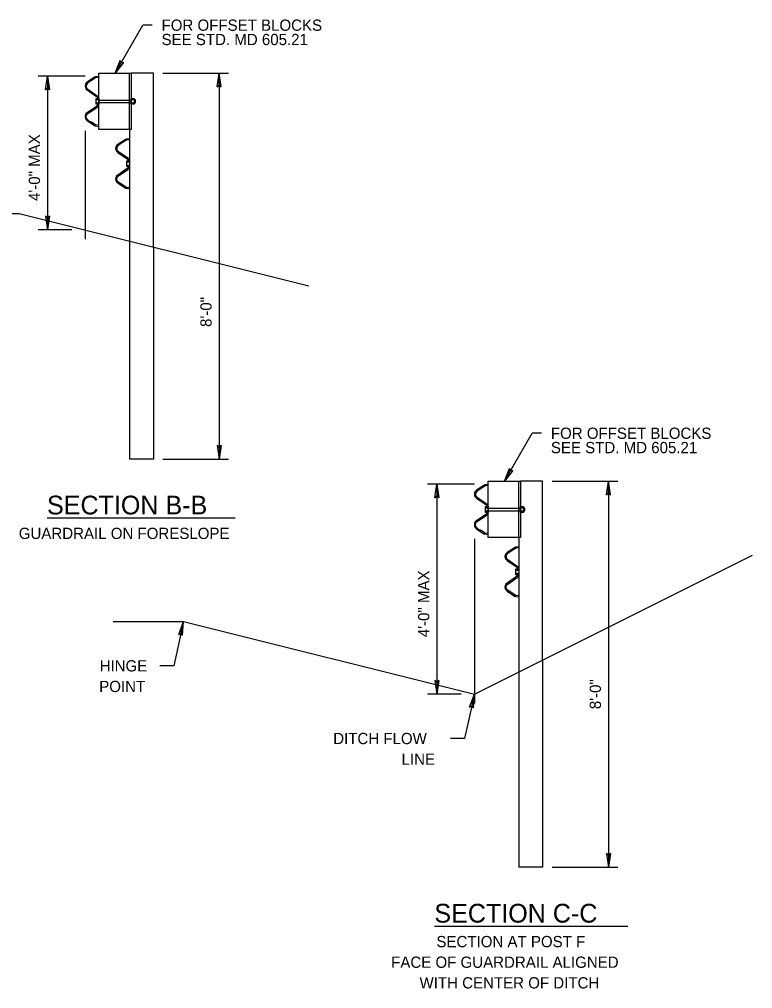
# Model space of a CAD drawing. Extents: x 12.4 to 19.6, y 6 to 16.
# Drawn here: x 15.21 to 19.12, y 10.87 to 16.04 of the extents above; entities that cross this region are included whole.
import ezdxf

# ---------------------------------------------------------------- set-up
doc = ezdxf.new("R2010")
doc.units = 0
for name, color, linetype in [('DETL-DIMS', 7, 'Continuous'), ('DETL-LINE', 7, 'Continuous'), ('DETL-NOTE', 7, 'Continuous'), ('DETL-TITL', 7, 'Continuous')]:
    doc.layers.add(name, color=color, linetype=linetype)

msp = doc.modelspace()

# ---------------------------------------------------------------- linework, layer by layer
at = {"layer": 'DETL-DIMS'}
for p, q in [((15.7215, 15.7508), (15.8695, 16.0071)), ((15.9195, 16.0071), (15.8695, 16.0071)), ((15.7487, 15.8191), (15.7215, 15.7508)), ((15.7487, 15.8191), (15.7534, 15.8059)), ((15.7671, 15.8085), (15.7215, 15.7508)), ((15.7671, 15.8085), (15.7534, 15.8059)), ((15.5615, 15.7349), (15.3115, 15.7349)), ((15.3509, 15.6621), (15.3615, 15.7349)), ((15.3615, 15.7349), (15.3615, 14.9156)), ((15.3721, 15.6621), (15.3615, 15.7349)), ((15.9757, 15.7508), (16.3264, 15.7508)), ((16.2658, 15.678), (16.2764, 15.7508)), ((16.2764, 15.7508), (16.2764, 13.6933)), ((16.287, 15.678), (16.2764, 15.7508)), ((15.3509, 15.6621), (15.3615, 15.6712)), ((15.3721, 15.6621), (15.3615, 15.6712)), ((16.2658, 15.678), (16.2764, 15.6871)), ((16.287, 15.678), (16.2764, 15.6871)), ((15.5615, 15.4441), (15.5615, 14.8656)), ((15.3509, 14.9884), (15.3615, 14.9156)), ((15.3509, 14.9884), (15.3615, 14.9793)), ((15.3721, 14.9884), (15.3615, 14.9156)), ((15.3721, 14.9884), (15.3615, 14.9793)), ((15.4915, 14.9156), (15.3115, 14.9156)), ((17.7972, 13.575), (17.9452, 13.8313)), ((17.9952, 13.8313), (17.9452, 13.8313)), ((16.2658, 13.7661), (16.2764, 13.6933)), ((16.2658, 13.7661), (16.2764, 13.757)), ((16.287, 13.7661), (16.2764, 13.6933)), ((16.287, 13.7661), (16.2764, 13.757)), ((15.9757, 13.6933), (16.3264, 13.6933)), ((17.8244, 13.6433), (17.7972, 13.575)), ((17.8244, 13.6433), (17.829, 13.6302)), ((17.8428, 13.6327), (17.7972, 13.575)), ((17.8428, 13.6327), (17.829, 13.6302)), ((17.6372, 13.5592), (17.3872, 13.5592)), ((17.4266, 13.4864), (17.4372, 13.5592)), ((17.4372, 13.5592), (17.4372, 12.44)), ((17.4478, 13.4864), (17.4372, 13.5592)), ((18.0513, 13.575), (18.402, 13.575)), ((18.3414, 13.5022), (18.352, 13.575)), ((18.352, 13.575), (18.352, 11.5175)), ((18.3626, 13.5022), (18.352, 13.575)), ((17.4266, 13.4864), (17.4372, 13.4955)), ((17.4478, 13.4864), (17.4372, 13.4955)), ((18.3414, 13.5022), (18.352, 13.5113)), ((18.3626, 13.5022), (18.352, 13.5113)), ((17.6372, 13.2683), (17.6372, 12.39)), ((16.0872, 12.8275), (16.0355, 12.5912)), ((16.0613, 12.7585), (16.0872, 12.8275)), ((16.082, 12.754), (16.0872, 12.8275)), ((16.0613, 12.7585), (16.0736, 12.7652)), ((16.082, 12.754), (16.0736, 12.7652)), ((16.0355, 12.5912), (15.9605, 12.5912)), ((17.4266, 12.5128), (17.4372, 12.44)), ((17.4266, 12.5128), (17.4372, 12.5037)), ((17.4478, 12.5128), (17.4372, 12.44)), ((17.4478, 12.5128), (17.4372, 12.5037)), ((17.5672, 12.44), (17.3872, 12.44)), ((17.6372, 12.44), (17.5855, 12.2037)), ((17.6113, 12.371), (17.6372, 12.44)), ((17.632, 12.3665), (17.6372, 12.44)), ((17.6113, 12.371), (17.6236, 12.3777)), ((17.632, 12.3665), (17.6236, 12.3777)), ((17.5855, 12.2037), (17.5105, 12.2037)), ((18.3414, 11.5903), (18.352, 11.5175)), ((18.3414, 11.5903), (18.352, 11.5812)), ((18.3626, 11.5903), (18.352, 11.5175)), ((18.3626, 11.5903), (18.352, 11.5812)), ((18.0513, 11.5175), (18.402, 11.5175))]:
    msp.add_line(p, q, dxfattribs=at)
for points in [[(15.7671, 15.8085), (15.7215, 15.7508), (15.7487, 15.8191), (15.7534, 15.8059)], [(15.3509, 15.6621), (15.3615, 15.7349), (15.3721, 15.6621), (15.3615, 15.6712)], [(16.287, 15.678), (16.2764, 15.7508), (16.2658, 15.678), (16.2764, 15.6871)], [(15.3509, 14.9884), (15.3615, 14.9156), (15.3721, 14.9884), (15.3615, 14.9793)], [(16.2658, 13.7661), (16.2764, 13.6933), (16.287, 13.7661), (16.2764, 13.757)], [(17.8428, 13.6327), (17.7972, 13.575), (17.8244, 13.6433), (17.829, 13.6302)], [(17.4266, 13.4864), (17.4372, 13.5592), (17.4478, 13.4864), (17.4372, 13.4955)], [(18.3626, 13.5022), (18.352, 13.575), (18.3414, 13.5022), (18.352, 13.5113)], [(16.082, 12.754), (16.0872, 12.8275), (16.0613, 12.7585), (16.0736, 12.7652)], [(17.4266, 12.5128), (17.4372, 12.44), (17.4478, 12.5128), (17.4372, 12.5037)], [(17.632, 12.3665), (17.6372, 12.44), (17.6113, 12.371), (17.6236, 12.3777)], [(18.3414, 11.5903), (18.352, 11.5175), (18.3626, 11.5903), (18.352, 11.5812)]]:
    msp.add_lwpolyline(points, close=True, dxfattribs=at)
at = {"layer": 'DETL-LINE'}
for p, q in [((15.799, 15.4508), (15.799, 15.7508)), ((15.6202, 15.6162), (15.6357, 15.6162)), ((15.6202, 15.5854), (15.6202, 15.6162)), ((15.6357, 15.6085), (15.6202, 15.6085)), ((15.6357, 15.6162), (15.6357, 15.5854)), ((15.6357, 15.6074), (15.8073, 15.6074)), ((15.8073, 15.6162), (15.8228, 15.6162)), ((15.8073, 15.5854), (15.8073, 15.6162)), ((15.8228, 15.6085), (15.8073, 15.6085)), ((15.8228, 15.6162), (15.8228, 15.5854)), ((15.8305, 15.6085), (15.8228, 15.6085)), ((15.8305, 15.5931), (15.8305, 15.6085)), ((15.6202, 15.593), (15.6357, 15.593)), ((15.6357, 15.5854), (15.6202, 15.5854)), ((15.6357, 15.5941), (15.8073, 15.5941)), ((15.8073, 15.5931), (15.8228, 15.5931)), ((15.8228, 15.5854), (15.8073, 15.5854)), ((15.8228, 15.5931), (15.8305, 15.5931)), ((15.7835, 15.2837), (15.799, 15.2837)), ((15.7835, 15.2529), (15.7835, 15.2837)), ((15.799, 15.276), (15.7835, 15.276)), ((15.7835, 15.2605), (15.799, 15.2605)), ((15.799, 15.2529), (15.7835, 15.2529)), ((15.799, 15.2837), (15.799, 15.2529)), ((15.799, 14.8562), (15.799, 13.6933)), ((15.9257, 14.8245), (15.9257, 13.6933)), ((15.9257, 13.6933), (15.799, 13.6933)), ((17.8747, 13.275), (17.8747, 13.575)), ((17.6959, 13.4404), (17.7113, 13.4404)), ((17.6959, 13.4096), (17.6959, 13.4404)), ((17.7113, 13.4404), (17.7113, 13.4096)), ((17.883, 13.4404), (17.8985, 13.4404)), ((17.883, 13.4096), (17.883, 13.4404)), ((17.8985, 13.4404), (17.8985, 13.4096)), ((17.7113, 13.4327), (17.6959, 13.4327)), ((17.6959, 13.4173), (17.7113, 13.4173)), ((17.7113, 13.4096), (17.6959, 13.4096)), ((17.7113, 13.4317), (17.883, 13.4317)), ((17.7113, 13.4183), (17.883, 13.4183)), ((17.8985, 13.4327), (17.883, 13.4327)), ((17.883, 13.4173), (17.8985, 13.4173)), ((17.8985, 13.4096), (17.883, 13.4096)), ((17.9062, 13.4327), (17.8985, 13.4327)), ((17.8985, 13.4173), (17.9062, 13.4173)), ((17.9062, 13.4173), (17.9062, 13.4327)), ((17.6372, 12.44), (19.1208, 13.1818)), ((17.8592, 13.1079), (17.8747, 13.1079)), ((17.8592, 13.0771), (17.8592, 13.1079)), ((17.8747, 13.1002), (17.8592, 13.1002)), ((17.8592, 13.0848), (17.8747, 13.0848)), ((17.8747, 13.0771), (17.8592, 13.0771)), ((17.8747, 13.1079), (17.8747, 13.0771)), ((15.7118, 12.8275), (16.0872, 12.8275)), ((16.0872, 12.8275), (17.6372, 12.44)), ((18.0013, 12.6221), (18.0013, 11.5175)), ((17.8747, 12.5587), (17.8747, 11.5175)), ((18.0013, 11.5175), (17.8747, 11.5175))]:
    msp.add_line(p, q, dxfattribs=at)
for points in [[(15.634, 15.7341), (15.6173, 15.7316), (15.6123, 15.7291), (15.5732, 15.7033), (15.5698, 15.7008), (15.5648, 15.6941), (15.5632, 15.6908)], [(15.6357, 15.7291), (15.619, 15.7266), (15.6182, 15.7258), (15.6165, 15.7258), (15.6157, 15.7249), (15.5765, 15.6991), (15.574, 15.6966), (15.569, 15.6899), (15.5682, 15.6866), (15.5673, 15.6824), (15.5682, 15.6783), (15.569, 15.6749), (15.5707, 15.6716), (15.5732, 15.6683), (15.5765, 15.6658), (15.6265, 15.6308), (15.6298, 15.6283), (15.6323, 15.6249), (15.6357, 15.6166), (15.6357, 15.6124), (15.6357, 15.6074)], [(15.6357, 15.7349), (15.634, 15.7341)], [(15.9257, 14.8245), (15.9257, 15.7508), (15.9215, 15.7508), (15.814, 15.7508), (15.8073, 15.7508)], [(15.5632, 15.6908), (15.5615, 15.6824), (15.5632, 15.6741)], [(15.5632, 15.6741), (15.5665, 15.6674), (15.5723, 15.6616), (15.6223, 15.6266), (15.6248, 15.6249), (15.6265, 15.6233), (15.6282, 15.6208), (15.629, 15.6191)], [(15.6298, 15.6162), (15.6298, 15.6166), (15.629, 15.6191)], [(15.6294, 15.5854), (15.629, 15.5841), (15.6282, 15.5808), (15.6265, 15.5783), (15.6223, 15.5741), (15.5723, 15.5399), (15.5665, 15.5341), (15.5648, 15.5308), (15.5632, 15.5266)], [(15.569, 15.5108), (15.5673, 15.5191), (15.5682, 15.5224), (15.569, 15.5266), (15.5707, 15.5299), (15.5732, 15.5333), (15.5765, 15.5358), (15.6265, 15.5699), (15.6298, 15.5733), (15.6323, 15.5766), (15.634, 15.5799), (15.6357, 15.5841), (15.6357, 15.5883), (15.6357, 15.5941)], [(15.5632, 15.5266), (15.5623, 15.5233), (15.5615, 15.5191), (15.5632, 15.5108)], [(15.5632, 15.5108), (15.5648, 15.5074), (15.5673, 15.5033), (15.5698, 15.5008), (15.5732, 15.4983), (15.6123, 15.4716), (15.614, 15.4708), (15.6157, 15.4699), (15.6173, 15.4699), (15.634, 15.4666)], [(15.6357, 15.4724), (15.619, 15.4749), (15.6182, 15.4749), (15.6165, 15.4758)], [(15.634, 15.4666), (15.6357, 15.4666)], [(15.7973, 15.4016), (15.7807, 15.3991), (15.779, 15.3983), (15.7773, 15.3983), (15.7757, 15.3966), (15.7365, 15.3708), (15.7332, 15.3683), (15.7282, 15.3616), (15.7265, 15.3583)], [(15.799, 15.4024), (15.7973, 15.4016)], [(15.799, 15.4508), (15.799, 14.8562)], [(15.7265, 15.3583), (15.7248, 15.3499), (15.7265, 15.3416)], [(15.799, 15.3966), (15.7823, 15.3941), (15.7815, 15.3933), (15.7807, 15.3933), (15.779, 15.3924), (15.7398, 15.3666), (15.7373, 15.3641), (15.7348, 15.3616), (15.7323, 15.3574), (15.7315, 15.3541)], [(15.7265, 15.3416), (15.7298, 15.3349), (15.7357, 15.3291), (15.7857, 15.2941), (15.7882, 15.2924), (15.7915, 15.2891), (15.7923, 15.2866)], [(15.7365, 15.3358), (15.7398, 15.3333), (15.7898, 15.2991), (15.7932, 15.2958), (15.7982, 15.2891), (15.799, 15.2849), (15.799, 15.2799), (15.799, 15.2749), (15.799, 15.2616), (15.799, 15.2624)], [(15.799, 15.1399), (15.7823, 15.1424), (15.7815, 15.1433), (15.7807, 15.1433), (15.779, 15.1441), (15.7398, 15.1699), (15.7373, 15.1724), (15.7348, 15.1749), (15.7323, 15.1791), (15.7315, 15.1824), (15.7315, 15.1899), (15.7323, 15.1941), (15.734, 15.1974), (15.7365, 15.2008), (15.7398, 15.2033), (15.7898, 15.2374), (15.7932, 15.2408), (15.7982, 15.2474), (15.799, 15.2516), (15.799, 15.2558), (15.799, 15.2616)], [(15.7932, 15.2837), (15.7932, 15.2841), (15.7923, 15.2866), (15.7932, 15.2841), (15.7932, 15.2837)], [(15.7265, 15.1949), (15.7248, 15.1866), (15.7265, 15.1783)], [(15.7882, 15.2441), (15.7857, 15.2424), (15.7357, 15.2074), (15.7298, 15.2016), (15.7265, 15.1949)], [(15.7265, 15.1783), (15.7282, 15.1749), (15.7307, 15.1708), (15.7332, 15.1683), (15.7365, 15.1658), (15.7757, 15.1391), (15.7773, 15.1383), (15.779, 15.1383), (15.7807, 15.1374), (15.7973, 15.1349)], [(15.7973, 15.1349), (15.799, 15.1341)], [(14.7828, 15.0033), (15.2107, 15.0033), (16.754, 14.6174)], [(17.7097, 13.5583), (17.693, 13.5558), (17.688, 13.5533), (17.6488, 13.5275), (17.6455, 13.525), (17.6405, 13.5183), (17.6388, 13.515)], [(17.7113, 13.5533), (17.6947, 13.5508), (17.6938, 13.55), (17.6922, 13.55), (17.6913, 13.5492), (17.6522, 13.5233), (17.6497, 13.5208), (17.6447, 13.5142), (17.6438, 13.5108), (17.643, 13.5067), (17.6438, 13.5025), (17.6447, 13.4992), (17.6463, 13.4958), (17.6488, 13.4925), (17.6522, 13.49), (17.7022, 13.455), (17.7055, 13.4525), (17.708, 13.4492), (17.7113, 13.4408), (17.7113, 13.4367), (17.7113, 13.4317)], [(17.7113, 13.5592), (17.7097, 13.5583)], [(18.0013, 12.6221), (18.0013, 13.575), (17.9972, 13.575), (17.8897, 13.575), (17.883, 13.575)], [(17.6388, 13.515), (17.6372, 13.5067), (17.6388, 13.4983)], [(17.6388, 13.4983), (17.6422, 13.4917), (17.648, 13.4858), (17.698, 13.4508), (17.7005, 13.4492), (17.7022, 13.4475), (17.7038, 13.445), (17.7047, 13.4433)], [(17.7055, 13.4404), (17.7055, 13.4408), (17.7047, 13.4433)], [(17.7051, 13.4096), (17.7047, 13.4083), (17.7038, 13.405), (17.7022, 13.4025), (17.698, 13.3983), (17.648, 13.3642), (17.6422, 13.3583), (17.6405, 13.355), (17.6388, 13.3508)], [(17.6447, 13.335), (17.643, 13.3433), (17.6438, 13.3467), (17.6447, 13.3508), (17.6463, 13.3542), (17.6488, 13.3575), (17.6522, 13.36), (17.7022, 13.3942), (17.7055, 13.3975), (17.708, 13.4008), (17.7097, 13.4042), (17.7113, 13.4083), (17.7113, 13.4125), (17.7113, 13.4183)], [(17.6388, 13.3508), (17.638, 13.3475), (17.6372, 13.3433), (17.6388, 13.335)], [(17.6388, 13.335), (17.6405, 13.3317), (17.643, 13.3275), (17.6455, 13.325), (17.6488, 13.3225), (17.688, 13.2958), (17.6897, 13.295), (17.6913, 13.2942), (17.693, 13.2942), (17.7097, 13.2908)], [(17.7113, 13.2967), (17.6947, 13.2992), (17.6938, 13.2992), (17.6922, 13.3)], [(17.7097, 13.2908), (17.7113, 13.2908)], [(17.8747, 13.275), (17.8747, 12.5587)], [(17.8022, 13.1825), (17.8005, 13.1742), (17.8022, 13.1658)], [(17.873, 13.2258), (17.8563, 13.2233), (17.8547, 13.2225), (17.853, 13.2225), (17.8513, 13.2208), (17.8122, 13.195), (17.8088, 13.1925), (17.8038, 13.1858), (17.8022, 13.1825)], [(17.8747, 13.2208), (17.858, 13.2183), (17.8572, 13.2175), (17.8563, 13.2175), (17.8547, 13.2167), (17.8155, 13.1908), (17.813, 13.1883), (17.8105, 13.1858), (17.808, 13.1817), (17.8072, 13.1783)], [(17.8747, 13.2267), (17.873, 13.2258)], [(17.8022, 13.1658), (17.8055, 13.1592), (17.8113, 13.1533), (17.8613, 13.1183), (17.8638, 13.1167), (17.8672, 13.1133), (17.868, 13.1108)], [(17.8122, 13.16), (17.8155, 13.1575), (17.8655, 13.1233), (17.8688, 13.12), (17.8738, 13.1133), (17.8747, 13.1092), (17.8747, 13.1042), (17.8747, 13.0992), (17.8747, 13.0858), (17.8747, 13.0867)], [(17.8747, 12.9642), (17.858, 12.9667), (17.8572, 12.9675), (17.8563, 12.9675), (17.8547, 12.9683), (17.8155, 12.9942), (17.813, 12.9967), (17.8105, 12.9992), (17.808, 13.0033), (17.8072, 13.0067), (17.8072, 13.0142), (17.808, 13.0183), (17.8097, 13.0217), (17.8122, 13.025), (17.8155, 13.0275), (17.8655, 13.0617), (17.8688, 13.065), (17.8738, 13.0717), (17.8747, 13.0758), (17.8747, 13.08), (17.8747, 13.0858)], [(17.8688, 13.1079), (17.8688, 13.1083), (17.868, 13.1108), (17.8688, 13.1083), (17.8688, 13.1079)], [(17.8638, 13.0683), (17.8613, 13.0667), (17.8113, 13.0317), (17.8055, 13.0258), (17.8022, 13.0192)], [(17.8022, 13.0192), (17.8005, 13.0108), (17.8022, 13.0025)], [(17.8022, 13.0025), (17.8038, 12.9992), (17.8063, 12.995), (17.8088, 12.9925), (17.8122, 12.99), (17.8513, 12.9633), (17.853, 12.9625), (17.8547, 12.9625), (17.8563, 12.9617), (17.873, 12.9592)], [(17.873, 12.9592), (17.8747, 12.9583)]]:
    msp.add_lwpolyline(points, dxfattribs=at)
for points in [[(15.6357, 15.4508), (15.6357, 15.7508), (15.8073, 15.7508), (15.8073, 15.4508)], [(17.7113, 13.275), (17.7113, 13.575), (17.883, 13.575), (17.883, 13.275)]]:
    msp.add_lwpolyline(points, close=True, dxfattribs=at)
for points in [[(15.569, 15.5108), (15.5804, 15.4942), (15.6028, 15.4895), (15.6165, 15.4758)], [(15.7315, 15.3541), (15.7316, 15.3456), (15.7305, 15.3429), (15.7365, 15.3358)], [(15.7882, 15.2441), (15.7911, 15.2467), (15.7925, 15.2496), (15.793, 15.2529)], [(17.6447, 13.335), (17.656, 13.3184), (17.6784, 13.3137), (17.6922, 13.3)], [(17.8072, 13.1783), (17.8072, 13.1698), (17.8062, 13.1671), (17.8122, 13.16)], [(17.8638, 13.0683), (17.8668, 13.0709), (17.8681, 13.0739), (17.8687, 13.0771)]]:
    msp.add_open_spline(points, degree=2, dxfattribs=at)
at = {"layer": 'DETL-TITL'}
for p, q in [((15.3588, 13.3802), (16.3618, 13.3802)), ((17.4241, 11.2038), (18.456, 11.2038))]:
    msp.add_line(p, q, dxfattribs=at)

# ---------------------------------------------------------------- texts
at = {"layer": 'DETL-NOTE'}
for s, rotation, p in [('FOR OFFSET BLOCKS', 360, (15.9695, 15.9771)), ('SEE STD. MD 605.21', 360, (15.9695, 15.9008)), ('4\'-0" MAX', 90, (15.3215, 15.0696)), ('8\'-0"', 90, (16.2364, 14.3981)), ('FOR OFFSET BLOCKS', 360, (18.0452, 13.8013)), ('SEE STD. MD 605.21', 360, (18.0452, 13.725)), ('GUARDRAIL ON FORESLOPE', 360, (15.2083, 13.2675)), ('4\'-0" MAX', 90, (17.3972, 12.7439)), ('HINGE', 360, (15.6393, 12.5612)), ('POINT', 360, (15.6372, 12.4512)), ('8\'-0"', 90, (18.312, 12.3601)), ('DITCH FLOW', 360, (16.8847, 12.1737)), ('LINE', 360, (17.2493, 12.0637)), ('SECTION AT POST F', 360, (17.435, 11.091)), ('FACE OF GUARDRAIL ALIGNED', 360, (17.1937, 10.981)), ('WITH CENTER OF DITCH', 360, (17.345, 10.871))]:
    msp.add_text(s, height=0.06, rotation=rotation, dxfattribs=at).set_placement(p)
at = {"layer": 'DETL-TITL'}
for s, p in [('SECTION B-B', (15.3588, 13.3985)), ('SECTION C-C', (17.4241, 11.2221))]:
    msp.add_text(s, height=0.1, rotation=360, dxfattribs=at).set_placement(p)

doc.saveas('drawing.dxf')
